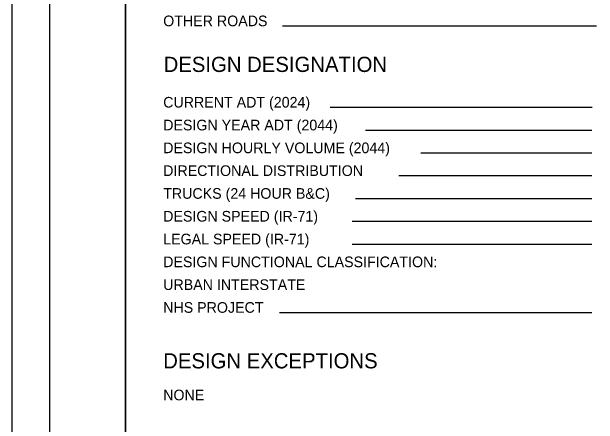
# Model space of a CAD drawing. Extents: x 0 to 34, y 0 to 22.
# Drawn here: x 0 to 7.72, y 5.64 to 11.07 of the extents above; entities that cross this region are included whole.
import ezdxf

# ---------------------------------------------------------------- set-up
doc = ezdxf.new("R2010")
doc.units = 0
for name, color, linetype in [('SH_Border', 7, 'Continuous'), ('SH_Cut_Line', 7, 'Continuous'), ('SH_Data', 7, 'Continuous'), ('SH_Text', 7, 'Continuous')]:
    doc.layers.add(name, color=color, linetype=linetype)

msp = doc.modelspace()

# ---------------------------------------------------------------- linework, layer by layer
at = {"layer": 'SH_Border'}
for points in [[(0.5, 21.5), (1.5, 21.5), (1.5, 0.5), (0.5, 0.5)], [(1.5, 21.5), (33.5, 21.5), (33.5, 0.5), (1.5, 0.5)]]:
    msp.add_lwpolyline(points, close=True, dxfattribs=at)
at = {"layer": 'SH_Cut_Line'}
msp.add_lwpolyline([(0, 0), (34, 0), (34, 22), (0, 22)], close=True, dxfattribs=at)
at = {"layer": 'SH_Data'}
for p, q in [((7.7, 10.8767), (3.5657, 10.8767)), ((7.6424, 9.8062), (4.1936, 9.8062)), ((7.6368, 9.5062), (4.6592, 9.5062)), ((7.6368, 9.2062), (5.3852, 9.2062)), ((7.6368, 8.9062), (5.0988, 8.9062)), ((7.6368, 8.6062), (4.5259, 8.6062)), ((7.6368, 8.3062), (4.483, 8.3062)), ((7.6368, 8.0062), (4.483, 8.0062)), ((7.6368, 7.1062), (3.5243, 7.1062))]:
    msp.add_line(p, q, dxfattribs=at)

# ---------------------------------------------------------------- texts
msp.add_text('DESIGN DESIGNATION', height=0.2, dxfattribs=at).set_placement((2, 10.2747))
at = {"layer": 'SH_Text'}
for s, height, p in [('OTHER ROADS', 0.14, (1.9944, 10.8767)), ('CURRENT ADT (2024)', 0.14, (1.9944, 9.8062)), ('DESIGN YEAR ADT (2044)', 0.14, (1.9944, 9.5062)), ('DESIGN HOURLY VOLUME (2044)', 0.14, (1.9944, 9.2062)), ('DIRECTIONAL DISTRIBUTION', 0.14, (1.9944, 8.9062)), ('TRUCKS (24 HOUR B&C)', 0.14, (1.9944, 8.6062)), ('DESIGN SPEED (IR-71)', 0.14, (1.9944, 8.3062)), ('LEGAL SPEED (IR-71)', 0.14, (1.9944, 8.0062)), ('DESIGN FUNCTIONAL CLASSIFICATION:', 0.14, (1.9944, 7.7062)), ('URBAN INTERSTATE', 0.14, (1.9944, 7.4062)), ('NHS PROJECT', 0.14, (1.9944, 7.1062)), ('DESIGN EXCEPTIONS', 0.2, (1.9944, 6.3744)), ('NONE', 0.14, (1.9944, 5.9544))]:
    msp.add_text(s, height=height, dxfattribs=at).set_placement(p)

doc.saveas('drawing.dxf')
